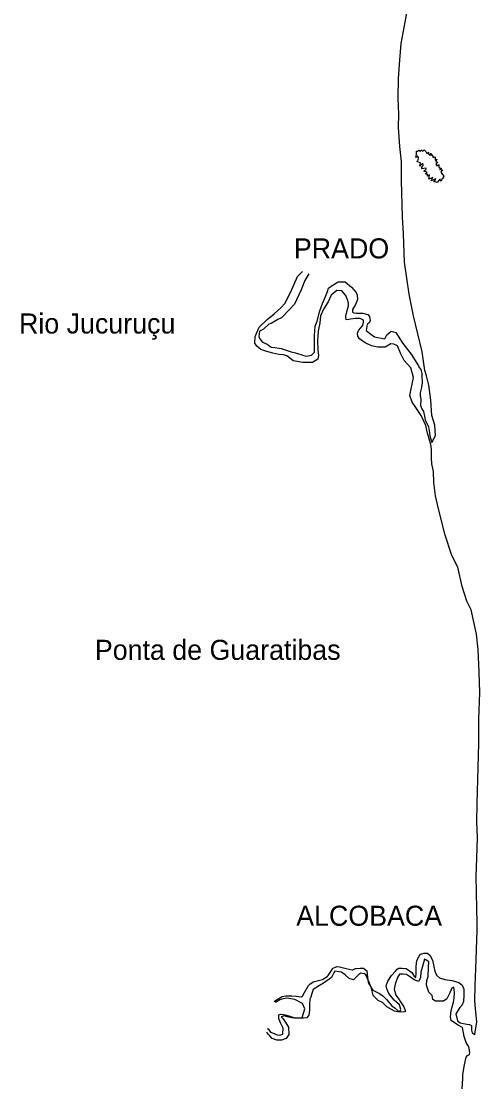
# Model space of a CAD drawing. Extents: x 662444 to 1640468, y 7452018 to 9606170.
# Drawn here: x 1102647 to 1117641, y 8048512 to 8083187 of the extents above; entities that cross this region are included whole.
import ezdxf

# ---------------------------------------------------------------- set-up
doc = ezdxf.new("R2010")
doc.units = 0
doc.layers.add('Level 1', color=7, linetype='Continuous')
doc.layers.add('Level 3', color=7, linetype='Continuous')

msp = doc.modelspace()

# ---------------------------------------------------------------- linework, layer by layer
at = {"layer": 'Level 1'}
for points in [[(1115709, 8070827), (1115702, 8070626), (1115745, 8070509), (1115797, 8070422), (1115831, 8070274), (1115850, 8070158), (1115959, 8069923), (1115992, 8069728), (1116012, 8069627), (1116068, 8069417), (1116191, 8069644), (1116170, 8069985), (1116072, 8070291), (1116040, 8070801), (1115971, 8071290), (1115895, 8071595), (1115846, 8071766), (1115757, 8072372), (1115475, 8073556), (1115334, 8074264), (1115181, 8075311), (1115147, 8076233), (1115110, 8076783), (1115085, 8077982), (1115082, 8078600), (1115027, 8079089), (1114984, 8079709), (1114989, 8080150), (1114974, 8080667), (1114978, 8081317), (1115021, 8081918), (1115068, 8082458), (1115206, 8083157), (1115271, 8083519)], [(1115979, 8078022), (1115988, 8078086), (1115998, 8078162), (1115930, 8078123), (1115932, 8078182), (1115868, 8078183), (1115925, 8078246), (1115816, 8078279), (1115890, 8078349), (1115875, 8078380), (1115746, 8078360), (1115758, 8078401), (1115725, 8078404), (1115788, 8078469), (1115774, 8078542), (1115679, 8078444), (1115701, 8078554), (1115584, 8078598), (1115610, 8078626), (1115638, 8078712), (1115615, 8078776), (1115554, 8078728), (1115567, 8078830), (1115572, 8078938), (1115618, 8078937), (1115650, 8078975), (1115697, 8078934), (1115728, 8078980), (1115783, 8078933), (1115825, 8078977), (1115877, 8078930), (1115904, 8078866), (1115963, 8078902), (1115962, 8078856), (1116013, 8078799), (1116037, 8078870), (1116048, 8078795), (1116082, 8078825), (1116119, 8078731), (1116178, 8078753), (1116177, 8078646), (1116240, 8078672), (1116206, 8078591), (1116268, 8078579), (1116207, 8078512), (1116236, 8078458), (1116304, 8078505), (1116304, 8078407), (1116393, 8078376), (1116320, 8078341), (1116420, 8078330), (1116369, 8078252), (1116419, 8078171), (1116481, 8078111), (1116440, 8078105), (1116452, 8078053), (1116407, 8078039), (1116375, 8077955), (1116332, 8078026), (1116248, 8077918), (1116210, 8077929), (1116159, 8077949), (1116138, 8077920), (1116204, 8078036), (1116052, 8077964), (1116103, 8078077), (1115979, 8078022)], [(1115531, 8070585), (1115426, 8070736), (1115348, 8070946), (1115475, 8071538), (1115385, 8071858), (1115166, 8072089), (1115050, 8072332), (1114949, 8072575), (1114827, 8072626), (1114734, 8072636), (1114552, 8072526), (1114305, 8072533), (1114104, 8072571), (1113890, 8072670), (1113709, 8072807), (1113657, 8072887), (1113637, 8072987), (1113671, 8073071), (1113750, 8073162), (1113815, 8073252), (1113841, 8073345), (1113843, 8073414), (1113730, 8073464), (1113574, 8073468), (1113418, 8073443), (1113356, 8073429), (1113270, 8073424), (1113259, 8073548), (1113303, 8073732), (1113347, 8073878), (1113349, 8073962), (1113321, 8074056), (1113257, 8074221), (1113130, 8074371), (1112967, 8074384), (1112777, 8074235), (1112685, 8074014), (1112530, 8073772), (1112438, 8073550), (1112408, 8073328), (1112361, 8073050), (1112336, 8072750), (1112342, 8072448), (1112367, 8072262), (1112347, 8072139), (1112174, 8072028), (1112089, 8072031), (1111856, 8072030), (1111541, 8072087), (1111420, 8072183), (1111336, 8072248), (1111221, 8072275), (1111066, 8072295), (1110874, 8072332), (1110681, 8072384), (1110483, 8072453), (1110346, 8072565), (1110287, 8072660), (1110295, 8072883), (1110428, 8073180), (1110690, 8073435), (1110921, 8073621), (1111136, 8073815), (1111274, 8073973), (1111496, 8074415), (1111680, 8074842), (1111839, 8074999)], [(1112054, 8074923), (1111924, 8074711), (1111798, 8074406), (1111582, 8073941), (1111414, 8073760), (1111158, 8073490), (1111040, 8073432), (1110819, 8073308), (1110740, 8073279), (1110573, 8073114), (1110439, 8073049), (1110419, 8072879), (1110447, 8072802), (1110537, 8072698), (1110690, 8072623), (1110818, 8072535), (1110942, 8072516), (1111143, 8072486), (1111472, 8072375), (1111610, 8072340), (1111886, 8072262), (1111979, 8072235), (1112143, 8072269), (1112231, 8072367), (1112240, 8072668), (1112240, 8072907), (1112257, 8073217), (1112324, 8073384), (1112412, 8073721), (1112497, 8073959), (1112579, 8074133), (1112664, 8074355), (1112698, 8074454), (1112817, 8074551), (1113006, 8074661), (1113239, 8074662), (1113443, 8074493), (1113600, 8074318), (1113636, 8074232), (1113639, 8074085), (1113573, 8073924), (1113507, 8073818), (1113482, 8073757), (1113480, 8073673), (1113526, 8073648), (1113603, 8073645), (1113819, 8073639), (1113982, 8073603), (1114034, 8073531), (1114052, 8073400), (1114036, 8073338), (1113956, 8073271), (1113926, 8073071), (1114040, 8072983), (1114199, 8072869), (1114537, 8072804), (1114596, 8072934), (1114739, 8073053), (1114893, 8073009), (1115122, 8072654), (1115279, 8072456), (1115398, 8072298), (1115634, 8071920), (1115663, 8071864), (1115715, 8071801), (1115742, 8071668), (1115747, 8071560), (1115757, 8071405), (1115756, 8071367), (1115736, 8071213), (1115692, 8071036), (1115689, 8070936), (1115709, 8070827)], [(1117049, 8051001), (1116985, 8050942), (1116862, 8050729), (1116909, 8050504), (1117000, 8050439), (1117216, 8050394), (1117300, 8050383), (1117369, 8050350), (1117365, 8050195), (1117392, 8050110), (1117484, 8050061), (1117504, 8050215), (1117542, 8050460), (1117503, 8050910), (1117479, 8051158), (1117494, 8051645), (1117513, 8052216), (1117531, 8052804), (1117543, 8053181), (1117551, 8053414), (1117553, 8053731), (1117543, 8054171), (1117537, 8054713), (1117522, 8055231), (1117541, 8055818), (1117562, 8056497), (1117546, 8057000), (1117559, 8057611), (1117612, 8059573), (1117614, 8060369), (1117641, 8061242), (1117622, 8061908), (1117592, 8062642), (1117530, 8063147), (1117354, 8063941), (1117222, 8064224), (1117060, 8064700), (1116924, 8065338), (1116727, 8065716), (1116501, 8066419), (1116260, 8067385), (1116191, 8067674), (1116143, 8068108), (1116123, 8068464), (1116077, 8068720), (1116060, 8068899), (1116061, 8069184), (1116035, 8069348), (1115930, 8069722), (1115875, 8069972), (1115723, 8070301), (1115531, 8070585)], [(1116709, 8050518), (1116681, 8050635), (1116704, 8050843), (1116729, 8050919), (1116782, 8051119), (1116802, 8051249), (1116815, 8051434), (1116796, 8051605), (1116726, 8051576), (1116660, 8051424), (1116561, 8051227), (1116449, 8051144), (1116195, 8051145), (1116103, 8051203), (1116084, 8051335), (1115971, 8051446), (1115901, 8051673), (1115906, 8051819), (1115948, 8051949), (1115966, 8052250), (1115972, 8052436), (1115881, 8052501), (1115834, 8052518), (1115783, 8052326), (1115713, 8052095), (1115707, 8051911), (1115634, 8051796), (1115496, 8051840), (1115375, 8051937), (1115246, 8052018), (1115130, 8052030), (1115014, 8052026), (1114949, 8051920), (1114873, 8051705), (1114837, 8051544), (1114893, 8051349), (1115004, 8051206), (1115048, 8051127), (1115159, 8050961), (1115202, 8050844), (1115200, 8050798), (1115038, 8050788), (1114853, 8050817), (1114602, 8050964), (1114458, 8051100), (1114315, 8051174), (1114156, 8051333), (1114103, 8051575), (1114030, 8051732), (1113914, 8052006), (1113870, 8052046), (1113754, 8052065), (1113691, 8052021), (1113603, 8051931), (1113515, 8051841), (1113369, 8051892), (1113234, 8052004), (1113120, 8052093), (1112905, 8052131), (1112880, 8052101), (1112789, 8051919), (1112536, 8051741), (1112402, 8051660), (1112197, 8051528), (1112154, 8051398), (1112119, 8051282), (1112086, 8051214), (1112074, 8051044), (1112068, 8050851), (1112047, 8050689), (1111990, 8050606), (1111873, 8050587), (1111726, 8050591), (1111587, 8050595), (1111487, 8050600), (1111348, 8050635), (1111257, 8050668), (1111147, 8050641), (1111147, 8050633), (1111215, 8050569), (1111311, 8050419), (1111384, 8050294), (1111400, 8050053), (1111311, 8049924), (1111155, 8049868), (1111000, 8049873), (1110854, 8049924), (1110779, 8050011), (1110719, 8050067), (1110675, 8050138)], [(1110916, 8051135), (1110994, 8051195), (1111176, 8051305), (1111300, 8051324), (1111494, 8051318), (1111633, 8051313), (1111810, 8051292), (1111810, 8051277), (1111849, 8051315), (1111907, 8051436), (1112038, 8051664), (1112079, 8051709), (1112197, 8051782), (1112493, 8051858), (1112524, 8051872), (1112660, 8051968), (1112684, 8051991), (1112813, 8052188), (1112829, 8052219), (1112971, 8052276), (1113056, 8052273), (1113271, 8052212), (1113471, 8052167), (1113486, 8052167), (1113573, 8052211), (1113728, 8052228), (1113837, 8052225), (1113949, 8052137), (1113967, 8051935), (1113992, 8051756), (1114110, 8051552), (1114147, 8051512), (1114360, 8051397), (1114466, 8051324), (1114586, 8051205), (1114766, 8050998), (1114879, 8050924), (1114969, 8050828), (1115039, 8050818), (1115063, 8050872), (1115014, 8051028), (1114841, 8051180), (1114662, 8051395), (1114597, 8051551), (1114577, 8051653), (1114636, 8051806), (1114758, 8051987), (1114886, 8052130), (1114934, 8052190), (1114990, 8052228), (1115105, 8052224), (1115237, 8052211), (1115419, 8052082), (1115499, 8051964), (1115553, 8051923), (1115557, 8052055), (1115565, 8052286), (1115578, 8052479), (1115660, 8052615), (1115701, 8052684), (1115809, 8052718), (1115926, 8052715), (1116009, 8052651), (1116090, 8052493), (1116137, 8052284), (1116171, 8052128), (1116221, 8051994), (1116327, 8051906), (1116503, 8051854), (1116741, 8051824), (1116957, 8051755), (1117062, 8051674), (1117120, 8051541), (1117114, 8051340), (1117108, 8051140), (1117049, 8051001)], [(1110686, 8050254), (1110717, 8050245), (1110799, 8050133), (1110860, 8050116), (1111013, 8050042), (1111105, 8050040), (1111199, 8050067), (1111213, 8050260), (1111140, 8050417), (1111068, 8050573), (1111069, 8050612), (1111072, 8050706), (1111127, 8050718), (1111220, 8050715), (1111281, 8050698), (1111396, 8050663), (1111562, 8050611), (1111738, 8050608), (1111828, 8050619), (1111915, 8050902), (1111849, 8051067), (1111591, 8051199), (1111329, 8051246), (1111165, 8051212), (1111103, 8051191), (1110961, 8051103)], [(1117064, 8048280), (1117083, 8048619), (1117086, 8048736), (1117126, 8049013), (1117170, 8049219), (1117197, 8049320), (1117238, 8049372), (1117308, 8049409), (1117310, 8049471), (1117285, 8049657), (1117197, 8049799), (1117126, 8049995), (1117080, 8050282), (1116913, 8050373), (1116709, 8050518)]]:
    msp.add_lwpolyline(points, dxfattribs=at)

# ---------------------------------------------------------------- texts
at = {"layer": 'Level 3'}
for s, height, p in [('PRADO', 655.3, (1111562, 8075432)), ('Rio Jucuruçu', 655.12, (1102575, 8072976)), ('Ponta de Guaratibas', 654.83, (1105056, 8062307)), ('ALCOBACA', 654.6, (1111640, 8053614))]:
    msp.add_text(s, height=height, dxfattribs=at).set_placement(p)

doc.saveas('drawing.dxf')
